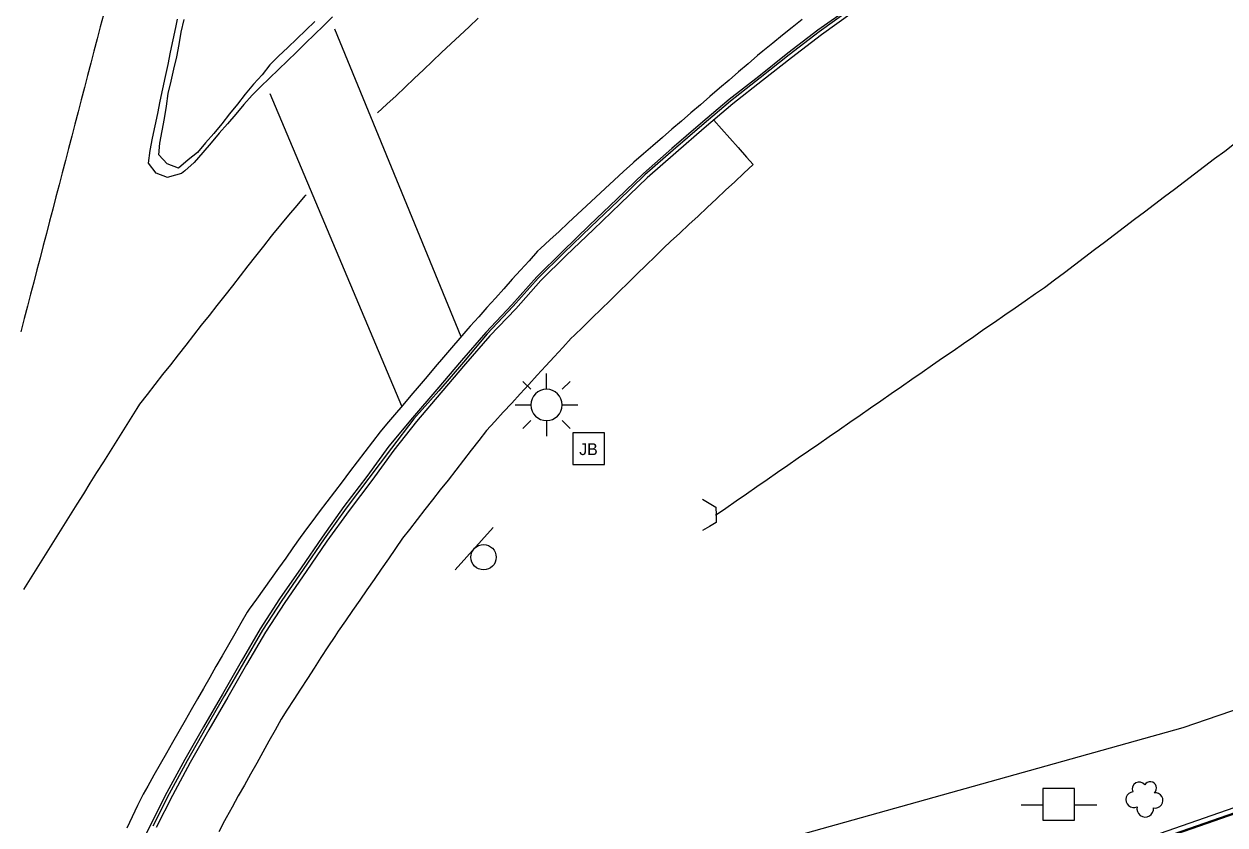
# Model space of a CAD drawing. Extents: x 1901471 to 1963503, y 756461 to 799997.
# Drawn here: x 1929649.4 to 1929745, y 772638.6 to 772702.4 of the extents above; entities that cross this region are included whole.
import ezdxf

# ---------------------------------------------------------------- set-up
doc = ezdxf.new("R2010")
doc.units = 0
for name, color, linetype in [('Default', 7, 'Continuous'), ('RD_EX_Bldg', 7, 'Continuous'), ('RD_EX_BldgApp', 7, 'Continuous'), ('RD_EX_Bridge', 7, 'Continuous'), ('RD_EX_Conc', 7, 'Continuous'), ('RD_EX_DR_Inlet', 7, 'Continuous'), ('RD_EX_Fence_Other', 7, 'Continuous'), ('RD_EX_H2O', 7, 'Continuous'), ('RD_EX_Road', 7, 'Continuous'), ('RD_EX_UT', 7, 'Continuous'), ('RD_EX_VEG', 7, 'Continuous')]:
    doc.layers.add(name, color=color, linetype=linetype)

# ---------------------------------------------------------------- blocks, each defined once
blk = doc.blocks.new('CB')
at = {"layer": 'Default'}
blk.add_lwpolyline([(0.1096, -0.1265), (0.0546, -0.0948), (0, -0.063), (0, 0), (0, 0.063), (0.0546, 0.0948), (0.1096, 0.1265)], dxfattribs=at)
blk = doc.blocks.new('PP')
at = {"layer": 'RD_EX_UT'}
for p, q in [((2.49, 2.51), (-2.51, 2.51)), ((-2.51, 2.51), (-2.51, -2.49)), ((2.49, -2.49), (2.49, 2.51)), ((-5.94, -0.05), (-2.47, -0.05)), ((2.42, -0.05), (6.06, -0.05)), ((-2.51, -2.49), (2.49, -2.49))]:
    blk.add_line(p, q, dxfattribs=at)
blk = doc.blocks.new('TSP')
at = {"layer": 'Default'}
for points in [[(0, 0.0635), (0, 0.127)], [(-0.0635, 0.0635), (-0.09525, 0.09525)], [(0.0635, 0.0635), (0.09525, 0.09525)], [(-0.127, 0), (-0.0635, 0)], [(0.0635, 0), (0.127, 0)], [(-0.0635, -0.0635), (-0.09525, -0.09525)], [(0, -0.0635), (0, -0.127)], [(0.0635, -0.0635), (0.09525, -0.09525)]]:
    blk.add_lwpolyline(points, dxfattribs=at)
for start, end in [(0, 180), (180, 0)]:
    blk.add_arc((0, 0), 0.0635, start, end, dxfattribs=at)
blk = doc.blocks.new('JB')
at = {"layer": 'RD_EX_DR_Inlet'}
blk.add_line((2.49, -2.5), (2.49, 2.5), dxfattribs=at)
blk.add_lwpolyline([(2.49, -2.5), (2.49, 2.5), (-2.51, 2.5), (-2.51, -2.5)], close=True, dxfattribs=at)
blk.add_text('JB', height=1.875, dxfattribs=at).set_placement((-1.48, -1.02))
blk = doc.blocks.new('SB2')
at = {"layer": 'RD_EX_VEG'}
for centre, radius, start, end in [((-0.72, 1.55), 1.08, 34.9763, 204.756), ((1.05, 1.7), 0.995, 308.7626, 152.0467), ((-1.56, -0.16), 1.26, 96.4518, 294.734), ((1.84, -0.28), 1.22, 256.5667, 98.1046), ((0.25, -1.6), 1.32, 166.8827, 5.7589)]:
    blk.add_arc(centre, radius, start, end, dxfattribs=at)
blk = doc.blocks.new('SIGN')
at = {"layer": 'RD_EX_BldgApp'}
blk.add_line((-4.52, -2.02), (4.48, -2.02), dxfattribs=at)
blk.add_circle((0, 0), 2, dxfattribs=at)

msp = doc.modelspace()

# ---------------------------------------------------------------- linework, layer by layer
at = {"layer": 'RD_EX_Conc'}
for points in [[(1929715.02, 772703.61), (1929712.57, 772701.88), (1929710.18, 772700.05), (1929707.87, 772698.21), (1929705.52, 772696.36), (1929703.23, 772694.42), (1929700.95, 772692.46), (1929698.7, 772690.48), (1929696.56, 772688.42), (1929694.39, 772686.35), (1929692.23, 772684.27), (1929690.19, 772682.25), (1929688.2, 772680.01), (1929686.14, 772677.82), (1929684.2, 772675.58), (1929682.25, 772673.29), (1929680.31, 772671.01), (1929678.43, 772668.76), (1929676.67, 772666.34), (1929674.85, 772663.95), (1929673.1, 772661.51), (1929671.44, 772659.07), (1929669.72, 772656.61), (1929668.18, 772654.21), (1929666.66, 772651.62), (1929665.17, 772649.02), (1929663.67, 772646.43), (1929662.18, 772643.82), (1929660.75, 772641.19), (1929659.45, 772638.61), (1929658.15, 772635.9)], [(1929715.12, 772703.5), (1929712.66, 772701.76), (1929710.28, 772699.93), (1929707.97, 772698.1), (1929705.62, 772696.24), (1929703.33, 772694.3), (1929701.05, 772692.34), (1929698.8, 772690.36), (1929696.67, 772688.31), (1929694.5, 772686.24), (1929692.34, 772684.16), (1929690.3, 772682.15), (1929688.31, 772679.9), (1929686.25, 772677.72), (1929684.35, 772675.45), (1929682.4, 772673.17), (1929680.41, 772670.93), (1929678.63, 772668.61), (1929676.83, 772666.21), (1929675.02, 772663.82), (1929673.26, 772661.39), (1929671.61, 772658.95), (1929669.89, 772656.49), (1929668.36, 772654.11), (1929666.84, 772651.52), (1929665.35, 772648.92), (1929663.85, 772646.33), (1929662.36, 772643.72), (1929660.93, 772641.08), (1929659.64, 772638.52)], [(1929715.3, 772703.27), (1929712.85, 772701.53), (1929710.47, 772699.7), (1929708.17, 772697.87), (1929705.81, 772696.02), (1929703.52, 772694.08), (1929701.25, 772692.12), (1929698.99, 772690.14), (1929696.87, 772688.09), (1929694.7, 772686.02), (1929692.54, 772683.94), (1929690.52, 772681.95), (1929688.53, 772679.71), (1929686.45, 772677.54), (1929684.51, 772675.31), (1929682.57, 772673.02), (1929680.62, 772670.74), (1929678.83, 772668.46), (1929677.06, 772666.03), (1929675.25, 772663.65), (1929673.49, 772661.21), (1929671.84, 772658.78), (1929670.13, 772656.32), (1929668.61, 772653.96), (1929667.09, 772651.37), (1929665.6, 772648.77), (1929664.1, 772646.18), (1929662.61, 772643.58), (1929661.19, 772640.94), (1929659.9, 772638.39)], [(1929672.54, 772702.59), (1929671.81, 772701.9), (1929671.09, 772701.2), (1929670.38, 772700.51), (1929669.65, 772699.82), (1929668.94, 772699.12), (1929668.33, 772698.32), (1929667.66, 772697.59), (1929666.99, 772696.79), (1929666.37, 772696.01), (1929665.73, 772695.23), (1929665.14, 772694.43), (1929664.49, 772693.66), (1929663.84, 772692.91), (1929663.19, 772692.15), (1929662.46, 772691.56), (1929661.69, 772690.91), (1929660.78, 772691.24), (1929660.11, 772691.97), (1929660.18, 772692.9), (1929660.38, 772693.88), (1929660.38, 772693.88), (1929660.57, 772694.86), (1929660.72, 772695.85), (1929660.86, 772696.84), (1929661.09, 772697.82), (1929661.3, 772698.79), (1929661.55, 772699.76), (1929661.73, 772700.75), (1929661.9, 772701.73), (1929662.13, 772702.73)], [(1929704.29, 772694.73), (1929704.9, 772694.04), (1929705.56, 772693.29), (1929706.22, 772692.54), (1929706.88, 772691.79), (1929707.41, 772691.19), (1929706.68, 772690.5), (1929705.95, 772689.82), (1929705.22, 772689.14), (1929704.49, 772688.46), (1929703.76, 772687.77), (1929703.03, 772687.09), (1929702.3, 772686.41), (1929701.57, 772685.73), (1929700.84, 772685.05), (1929700.32, 772684.57), (1929699.61, 772683.87), (1929698.89, 772683.17), (1929698.17, 772682.47), (1929697.46, 772681.77), (1929696.74, 772681.07), (1929696.03, 772680.37), (1929695.31, 772679.68), (1929694.6, 772678.98), (1929693.88, 772678.28), (1929693.17, 772677.58), (1929692.94, 772677.36), (1929692.26, 772676.62), (1929691.59, 772675.88), (1929690.91, 772675.15), (1929690.23, 772674.41), (1929689.56, 772673.68), (1929688.88, 772672.94), (1929688.21, 772672.2), (1929687.53, 772671.47), (1929686.85, 772670.73), (1929686.2, 772670.02), (1929685.58, 772669.23), (1929684.97, 772668.44), (1929684.36, 772667.65), (1929683.74, 772666.86), (1929683.13, 772666.07), (1929682.51, 772665.28), (1929681.9, 772664.49), (1929681.28, 772663.71), (1929680.67, 772662.92), (1929680.06, 772662.13), (1929679.52, 772661.43), (1929678.95, 772660.61), (1929678.38, 772659.79), (1929677.81, 772658.97), (1929677.24, 772658.15), (1929676.67, 772657.32), (1929676.1, 772656.5), (1929675.53, 772655.68), (1929674.96, 772654.86), (1929674.39, 772654.03), (1929674.11, 772653.62), (1929673.57, 772652.78), (1929673.02, 772651.94), (1929672.48, 772651.1), (1929671.94, 772650.26), (1929671.4, 772649.42), (1929670.85, 772648.59), (1929670.31, 772647.75), (1929670.31, 772647.75), (1929669.84, 772647.02), (1929669.36, 772646.15), (1929668.87, 772645.28), (1929668.38, 772644.4), (1929667.9, 772643.53), (1929667.41, 772642.65), (1929666.92, 772641.78), (1929666.44, 772640.91), (1929665.95, 772640.03), (1929665.47, 772639.16), (1929665.34, 772638.93), (1929664.88, 772638.05)], [(1929818.65, 772665.59), (1929787.63, 772654.66), (1929748.03, 772640.8), (1929705.53, 772625.99), (1929700.95, 772619.84), (1929709.34, 772614.36), (1929711.28, 772612.96), (1929711.56, 772612.25), (1929711.57, 772611.67), (1929711.15, 772611.01), (1929710.56, 772610.45), (1929709.71, 772610.24), (1929708.74, 772610.02), (1929689.83, 772613.26), (1929674.02, 772596.83), (1929647.69, 772569.61)], [(1929818.56, 772665.14), (1929787.76, 772654.28), (1929748.16, 772640.43), (1929705.78, 772625.66), (1929701.53, 772619.94), (1929709.57, 772614.69), (1929711.61, 772613.22), (1929711.96, 772612.32), (1929711.97, 772611.56), (1929711.46, 772610.75), (1929710.77, 772610.09), (1929709.81, 772609.85), (1929708.75, 772609.61), (1929689.97, 772612.83), (1929674.31, 772596.55), (1929648.04, 772569.39)], [(1929818.54, 772665.03), (1929787.79, 772654.19), (1929748.2, 772640.33), (1929705.84, 772625.57), (1929701.67, 772619.96), (1929709.62, 772614.77), (1929711.7, 772613.28), (1929712.06, 772612.34), (1929712.07, 772611.53), (1929711.54, 772610.69), (1929710.82, 772610), (1929709.83, 772609.75), (1929708.75, 772609.51), (1929690.01, 772612.73), (1929674.38, 772596.48), (1929648.13, 772569.34)]]:
    msp.add_lwpolyline(points, dxfattribs=at)
at = {"layer": 'RD_EX_Fence_Other'}
msp.add_lwpolyline([(1930230.69, 773075.39), (1930202.12, 773046.67), (1930160.84, 773005.63), (1930128.22, 772972.13), (1930093.2, 772937.02), (1930073.43, 772918.59), (1930046.34, 772888.73), (1930044.81, 772868.05), (1930041.7, 772840.72), (1929994.8, 772796.32), (1929941.04, 772746.6), (1929894.33, 772713.92), (1929883.55, 772706.62), (1929817.78, 772673.24), (1929792.5, 772663.78), (1929741.61, 772646.35), (1929701.32, 772635.07), (1929691.74, 772624.27), (1929671.21, 772603.84), (1929649.68, 772579.5)], dxfattribs=at)
at = {"layer": 'RD_EX_H2O'}
msp.add_lwpolyline([(1929704.42, 772663.27), (1929705.24, 772663.84), (1929706.06, 772664.41), (1929706.88, 772664.98), (1929707.71, 772665.55), (1929708.53, 772666.12), (1929709.35, 772666.69), (1929710.17, 772667.26), (1929710.99, 772667.83), (1929711.82, 772668.4), (1929712.64, 772668.96), (1929713.46, 772669.53), (1929714.28, 772670.1), (1929715.11, 772670.67), (1929715.93, 772671.24), (1929716.75, 772671.81), (1929717.57, 772672.38), (1929718.39, 772672.95), (1929719.22, 772673.52), (1929720.04, 772674.09), (1929720.86, 772674.66), (1929721.68, 772675.23), (1929722.5, 772675.8), (1929723.33, 772676.36), (1929724.15, 772676.93), (1929724.97, 772677.5), (1929725.79, 772678.07), (1929726.62, 772678.64), (1929727.44, 772679.21), (1929728.26, 772679.78), (1929729.08, 772680.35), (1929729.9, 772680.92), (1929730.6, 772681.4), (1929731.39, 772682), (1929732.19, 772682.6), (1929732.99, 772683.21), (1929733.78, 772683.81), (1929734.58, 772684.42), (1929735.38, 772685.02), (1929736.18, 772685.62), (1929736.97, 772686.23), (1929737.77, 772686.83), (1929738.57, 772687.43), (1929739.36, 772688.04), (1929740.16, 772688.64), (1929740.96, 772689.24), (1929741.76, 772689.85), (1929742.55, 772690.45), (1929743.35, 772691.06), (1929744.15, 772691.66), (1929744.95, 772692.26), (1929745.74, 772692.87)], dxfattribs=at)
at = {"layer": 'RD_EX_Road'}
for points in [[(1929655.7, 772703.12), (1929655.45, 772702.16), (1929655.2, 772701.19), (1929654.94, 772700.22), (1929654.69, 772699.25), (1929654.44, 772698.29), (1929654.19, 772697.32), (1929653.94, 772696.35), (1929653.68, 772695.38), (1929653.43, 772694.41), (1929653.18, 772693.45), (1929652.93, 772692.48), (1929652.68, 772691.51), (1929652.42, 772690.54), (1929652.17, 772689.58), (1929651.92, 772688.61), (1929651.67, 772687.64), (1929651.42, 772686.67), (1929651.16, 772685.71), (1929651.16, 772685.71), (1929650.91, 772684.74), (1929650.66, 772683.77), (1929650.41, 772682.8), (1929650.16, 772681.83), (1929649.9, 772680.87), (1929649.65, 772679.9), (1929649.4, 772678.93), (1929649.12, 772677.88)], [(1929711.31, 772702.74), (1929710.53, 772702.11), (1929709.76, 772701.48), (1929708.98, 772700.85), (1929708.2, 772700.22), (1929707.77, 772699.87), (1929707.01, 772699.22), (1929706.25, 772698.56), (1929705.5, 772697.91), (1929704.74, 772697.26), (1929703.98, 772696.61), (1929703.22, 772695.95), (1929702.46, 772695.3), (1929701.71, 772694.65), (1929700.95, 772694), (1929700.19, 772693.34), (1929699.43, 772692.69), (1929698.68, 772692.04), (1929697.92, 772691.39), (1929697.83, 772691.31), (1929697.1, 772690.63), (1929696.36, 772689.95), (1929695.63, 772689.27), (1929694.9, 772688.59), (1929694.16, 772687.91), (1929693.43, 772687.23), (1929692.7, 772686.55), (1929691.97, 772685.87), (1929691.23, 772685.19), (1929690.5, 772684.51), (1929690.24, 772684.28), (1929689.58, 772683.53), (1929688.91, 772682.79), (1929688.24, 772682.05), (1929687.57, 772681.3), (1929686.9, 772680.56), (1929686.23, 772679.81), (1929685.57, 772679.07), (1929684.9, 772678.33), (1929684.72, 772678.12), (1929684.07, 772677.36), (1929683.42, 772676.6), (1929682.77, 772675.84), (1929682.12, 772675.08), (1929681.47, 772674.32), (1929680.83, 772673.56), (1929680.18, 772672.8), (1929679.53, 772672.03), (1929678.88, 772671.27), (1929678.23, 772670.51), (1929677.72, 772669.91), (1929677.12, 772669.11), (1929676.51, 772668.32), (1929675.91, 772667.52), (1929675.3, 772666.72), (1929674.7, 772665.93), (1929674.09, 772665.13), (1929673.49, 772664.34), (1929672.88, 772663.54), (1929672.28, 772662.74), (1929671.94, 772662.3), (1929671.36, 772661.49), (1929670.78, 772660.67), (1929670.21, 772659.85), (1929669.63, 772659.04), (1929669.05, 772658.22), (1929668.47, 772657.41), (1929667.89, 772656.59), (1929667.31, 772655.78), (1929667.15, 772655.55), (1929666.65, 772654.68), (1929666.16, 772653.82), (1929665.66, 772652.95), (1929665.16, 772652.08), (1929664.66, 772651.21), (1929664.16, 772650.35), (1929663.66, 772649.48), (1929663.19, 772648.65), (1929662.69, 772647.78), (1929662.2, 772646.91), (1929661.7, 772646.05), (1929661.21, 772645.18), (1929660.71, 772644.31), (1929660.22, 772643.44), (1929659.72, 772642.57), (1929659.23, 772641.7), (1929658.86, 772641.06), (1929658.42, 772640.15), (1929657.99, 772639.25), (1929657.56, 772638.35)], [(1929673.94, 772702.94), (1929673.22, 772702.24), (1929672.5, 772701.55), (1929671.78, 772700.85), (1929671.07, 772700.15), (1929670.35, 772699.46), (1929669.63, 772698.76), (1929668.91, 772698.07), (1929668.2, 772697.37), (1929667.53, 772696.72), (1929666.88, 772695.96), (1929666.23, 772695.2), (1929665.58, 772694.44), (1929664.92, 772693.68), (1929664.27, 772692.92), (1929663.62, 772692.16), (1929662.92, 772691.34), (1929662.17, 772690.69), (1929661.92, 772690.48), (1929660.96, 772690.2), (1929660.96, 772690.2), (1929660.79, 772690.16), (1929659.89, 772690.51), (1929659.29, 772691.29), (1929659.41, 772692.32), (1929659.61, 772693.3), (1929659.82, 772694.27), (1929660.02, 772695.25), (1929660.23, 772696.23), (1929660.43, 772697.21), (1929660.64, 772698.19), (1929660.85, 772699.16), (1929661.05, 772700.14), (1929661.26, 772701.12), (1929661.46, 772702.1), (1929661.6, 772702.77)], [(1929677.53, 772695.3), (1929678.26, 772695.99), (1929678.99, 772696.67), (1929679.71, 772697.36), (1929680.44, 772698.04), (1929681.17, 772698.73), (1929681.9, 772699.42), (1929682.62, 772700.1), (1929683.35, 772700.79), (1929684.08, 772701.47), (1929684.81, 772702.16), (1929685.53, 772702.85)], [(1929684.17, 772677.48), (1929674.13, 772701.97)], [(1929679.46, 772671.95), (1929668.98, 772696.82)], [(1929649.36, 772657.36), (1929649.89, 772658.2), (1929650.42, 772659.05), (1929650.95, 772659.9), (1929651.48, 772660.75), (1929652.01, 772661.59), (1929652.54, 772662.44), (1929653.07, 772663.29), (1929653.6, 772664.14), (1929654.13, 772664.98), (1929654.66, 772665.83), (1929655.19, 772666.68), (1929655.73, 772667.53), (1929656.26, 772668.37), (1929656.79, 772669.22), (1929657.32, 772670.07), (1929657.85, 772670.92), (1929658.38, 772671.76), (1929658.59, 772672.1), (1929659.21, 772672.89), (1929659.82, 772673.67), (1929660.44, 772674.46), (1929661.06, 772675.25), (1929661.67, 772676.03), (1929662.29, 772676.82), (1929662.91, 772677.61), (1929663.52, 772678.39), (1929664.14, 772679.18), (1929664.76, 772679.97), (1929665.38, 772680.75), (1929665.99, 772681.54), (1929666.61, 772682.33), (1929667.23, 772683.12), (1929667.84, 772683.9), (1929668.46, 772684.69), (1929669.08, 772685.48), (1929669.19, 772685.62), (1929669.83, 772686.38), (1929670.47, 772687.15), (1929671.11, 772687.92), (1929671.75, 772688.69), (1929671.83, 772688.79)]]:
    msp.add_lwpolyline(points, dxfattribs=at)

# ---------------------------------------------------------------- block references
at = {"layer": 'Default', "xscale": 0.5039370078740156, "yscale": 0.5039370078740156}
for name, p in [('JB', (1929694.32, 772668.57)), ('PP', (1929731.73, 772640.24))]:
    msp.add_blockref(name, p, dxfattribs=at)
at = {"layer": 'RD_EX_Bldg', "xscale": 0.5039370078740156, "yscale": 0.5039370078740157, "rotation": -131.804489}
msp.add_blockref('SIGN', (1929685.96, 772659.92), dxfattribs=at)
at = {"layer": 'RD_EX_Bridge', "xscale": 9.84251968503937, "yscale": 9.84251968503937, "rotation": -179.587783}
msp.add_blockref('CB', (1929704.46, 772663.3), dxfattribs=at)
at = {"layer": 'RD_EX_UT', "xscale": 19.68503937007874, "yscale": 19.68503937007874}
msp.add_blockref('TSP', (1929690.97, 772672.05), dxfattribs=at)
at = {"layer": 'RD_EX_VEG', "xscale": 0.5019685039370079, "yscale": 0.5019685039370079}
msp.add_blockref('SB2', (1929738.5, 772640.7), dxfattribs=at)

doc.saveas('drawing.dxf')
